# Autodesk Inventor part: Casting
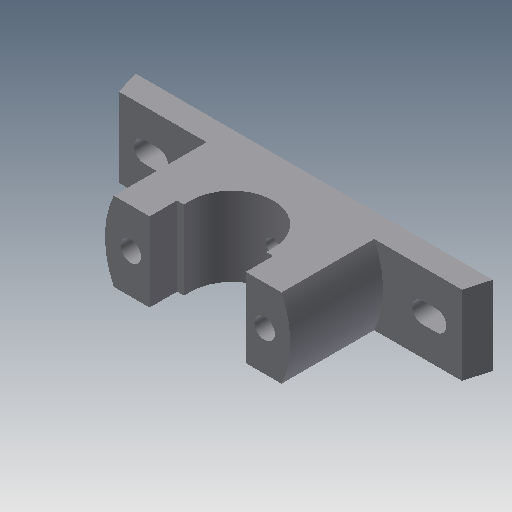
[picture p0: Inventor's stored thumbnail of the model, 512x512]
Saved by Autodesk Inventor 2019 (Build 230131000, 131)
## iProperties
Created: 2009-04
Part Number: Casting
Document SubType Name: Modeling
Designer: Sham
Density: 1 g/cm^3
Material: Generic
Appearance: Default
Author: Sham
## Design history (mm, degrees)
sketch "Sketch1"
  geometry: L1 (-104, 0)-(104, 0); L2 (-104, 0)-(-100, 14); L3 (-100, 14)-(100, 14); L4 (100, 14)-(104, 0); 1 further point
  constraints: 8 end point, 1 horizontal, 1 midpoint, 1 parallel, 1 other
  dimensions: "d0" = 208 distance of L1.start L1.end; "d1" = 104 distance of L1.end point (0, 0); "d2" = 4 horizontal distance of L1.start L2.end; "d3" = 4 horizontal distance of L1.end L3.end; "d10" = 14 distance between parallel lines of L1 L3
extrude "Extrusion1" new body sketch "Sketch1" stored distance "d4" = 46; taper "d5" = 0 deg
sketch "Sketch2"
  geometry: L1 (51.143, 46)-(148.857, 46); L2 (148.857, 0)-(51.143, 0); A1 r 54 centre (100, 23) between (51.143, 46) and (51.143, 0); A2 r 54 centre (100, 23) between (148.857, 0) and (148.857, 46)
  constraints: 4 end point, 4 point on circle, 2 centre point, 1 parallel
extrude "Extrusion2" join sketch "Sketch2" distance "d8" = 54; taper "d9" = 0 deg
sketch "Sketch3"
  geometry: L1 (-28, 68)-(-28, 52); L2 (-28, 52)-(-24, 52); L3 (28, 68)-(28, 52); L4 (28, 52)-(24, 52); L5 (-28, 68)-(28, 68); L6 (-100, 14)-(-48.857, 14) reference; L7 (0, 48)-(0, 19); L8 (48.857, 14)-(100, 14) reference; L9 (48.857, 68)-(-48.857, 68) reference; L10 (-24, 48)-(-24, 52); L11 (24, 48)-(24, 52); A1 r 24 centre (0, 48) between (-24, 48) and (24, 48); 1 further point
  constraints: 16 end point, 5 perpendicular, 2 point on circle, 2 symmetric about line, 1 centre point, 1 tangent, 1 vertical alignment, 1 other
  dimensions: "d11" = 16 distance of L1.start L1.end; "d16" = 24 radius of A1; "d17" = 16 distance of L3.start L3.end; "d52" = 56 distance between parallel lines of L1 L3; "d54" = 54 distance between parallel lines of L8 L9 (derived)
extrude "Extrusion3" cut sketch "Sketch3" distance "d18" = 54; taper "d19" = 0 deg
sketch "Sketch4"
  geometry: L1 (-23, 29)-(-15, 29); L2 (-15, 17)-(-23, 17); L3 (-185, 29)-(-177, 29); L4 (-177, 17)-(-185, 17); A1 r 6 centre (-15, 23) between (-15, 17) and (-15, 29); A2 r 6 centre (-23, 23) between (-23, 29) and (-23, 17); A3 r 6 centre (-177, 23) between (-177, 17) and (-177, 29); A4 r 6 centre (-185, 23) between (-185, 29) and (-185, 17)
  constraints: 8 end point, 8 point on circle, 8 tangent, 4 centre point, 3 parallel
  dimensions: "d20" = 8 distance of A1.centre A2.centre; "d21" = 6 radius of A1; "d24" = 6 radius of A3; "d25" = 8 distance of A4.centre A3.centre
extrude "Extrusion4" cut sketch "Sketch4" distance "d28" = 54; taper "d29" = 0 deg
sketch "Sketch5"
  geometry: L1 (208, 0)-(0, 0) reference; L2 (52, -10)-(78, -10); L3 (78, -10)-(78, -36); L4 (78, -36)-(52, -36); L5 (52, -36)-(52, -10); L6 (130, -10)-(156, -10); L7 (156, -10)-(156, -36); L8 (156, -36)-(130, -36); L9 (130, -36)-(130, -10); L10 (0, -46)-(208, -46) reference; L11 (104, -23)-(104, -46)
  constraints: 18 end point, 5 perpendicular, 4 parallel, 2 horizontal, 1 midpoint
  dimensions: "d30" = 26 distance of L2.start L2.end; "d31" = 10 distance between parallel lines of L2 L1; "d32" = 10 distance between parallel lines of L1 L6; "d65" = 26 distance between parallel lines of L3 L11; "d66" = 26 distance between parallel lines of L9 L11
extrude "Extrusion5" cut sketch "Sketch5" distance "d34" = 10; taper "d35" = 0 deg
sketch "Sketch6"
  geometry: L1 (148.857, 0)-(128, 0) reference; L2 (72, 0)-(51.143, 0) reference; L3 (0, 46)-(0, 0) reference; L4 (200, 46)-(200, 0) reference; C1 r 6 at (61, 23); C2 r 6 at (139, 23); 1 further point
  constraints: 2 centre point, 1 equal radius
  dimensions: "d36" = 12 diameter of C1; "d37" = 78 distance of C2.centre C1.centre; "d39" = 39 distance of C2.centre point (100, 23); "d58" = 39 distance of C1.centre point (100, 23); "d59" = 23 distance from line of L1 C2.centre; "d60" = 23 distance from line of L2 C1.centre; "d61" = 61 distance from line of L3 C1.centre; "d62" = 61 distance from line of L4 C2.centre (derived)
extrude "Extrusion6" cut sketch "Sketch6" extent not by distance; stored distance "d40" = 10; taper "d41" = 0 deg
workplane "Work Plane1"
sketch "Sketch7"
  geometry: L1 (-4, 46)-(204, 46) reference; L2 (-4, 0)-(-4, 46) reference; 1 further point
  dimensions: "d43" = 23 distance from line of L1 point (100, 23); "d44" = 104 distance from line of point (100, 23) L2
hole "Hole1" sketch "Sketch7" at (100, 23) diameter "d45" = 8; stored, may be unused: countersink angle "d49" = 90 deg, drill point angle "d51" = 118 deg; dims "d46" = 6, "d47" = 8, "d48" = 16, "d50" = 8
body "Solid1"
other parameters: "d6" = 108, "d42" = -52
